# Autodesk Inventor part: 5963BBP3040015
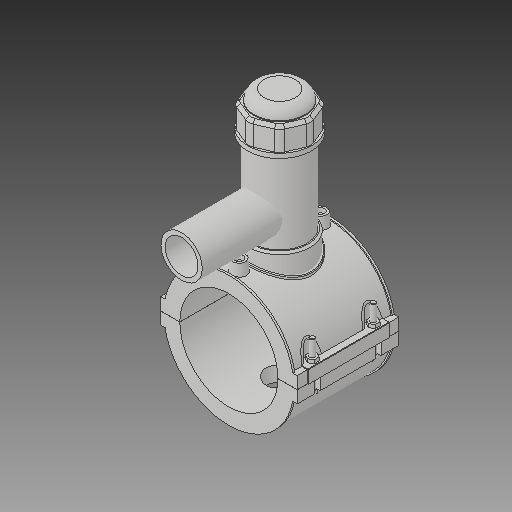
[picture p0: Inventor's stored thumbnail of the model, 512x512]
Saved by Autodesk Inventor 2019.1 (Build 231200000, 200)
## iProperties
Created: 2017-07
Part Number: 5963BBP3040015
Material: Generic
Description: PLASSON TAPPING SADDLE 4''IPS x 1 1/2''IPS
Document SubType Name: Modeling
Designer: KIM
Density: 1 g/cm^3
Appearance: Default
Author: KIM
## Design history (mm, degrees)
derived "5963BBP_5963BUP.ipt"
feature "Solid1::5963BBP_5963BUP.ipt"
feature "Solid2::5963BBP_5963BUP.ipt"
feature "Solid3::5963BBP_5963BUP.ipt"
tag "TaggingFeature1"
body "Solid1"
body "Solid2"
body "Solid3"
other parameters: "d0" = 114.1, "d2" = 159.004, "d3" = 28.525, "d4" = 118.11, "d5" = 0, "d6" = 0.1, "d8" = 0, "d19" = 6, "d20" = 6, "d21" = 70.866, "d23" = 0, "d24" = 35.433, "d26" = 0, "d27" = 3, "d28" = 3, "d29" = 3, "d30" = 38.03333, "d31" = 6, "d32" = 0, "d33" = 0, "d34" = 0.6, "d40" = 77.1316, "d41" = 74.165, "d43" = 0, "d45" = 0, "d47" = 145.031, "d70" = 15, "d72" = 0, "d73" = 6, "d75" = 5, "d76" = 0, "d77" = 5.705, "d78" = 87.05, "d79" = 15, "d80" = 47.244, "d82" = 5 deg, "d84" = 4, "d85" = 14, "d86" = 0, "d87" = 3, "d88" = 0, "d89" = 1, "d90" = 1, "d91" = 94.488, "d92" = 0, "d93" = 0.5, "d94" = 60.05263, "d96" = 151.2966, "d97" = 2.3622, "d98" = 0, "d102" = 1.141, "d120" = 140 deg, "d121" = 24.228, "d122" = 20 deg, "d123" = 296.66, "d124" = 88.998, "d126" = 0, "d143" = 117.523, "d145" = 26.33077, "d149" = 1.7115, "d150" = 28.96385, "d153" = 118.11, "d154" = 0, "d156" = 74.165, "d157" = 160 deg, "d159" = 6.846, "d161" = 1.7115, "d162" = 70.866, "d163" = 0, "d164" = 57.05, "d167" = 11.41, "d168" = 72.3561, "d170" = 3.2805, "d172" = 0, "d173" = 1, "d175" = 57.05, "d176" = 20 deg, "d177" = 7.987, "d178" = 34.23, "d180" = 0, "d183" = 13.692, "d184" = 6.3896, "d185" = 38.38575, "d186" = 38.38575, "d187" = 74.165, "d188" = 10.269, "d189" = 7.987, "d190" = 0, "d191" = 111.2475, "d193" = 6.9984, "d194" = 4.13385, "d195" = 90 deg, "d197" = 0, "d199" = 0, "d200" = 17.115, "d202" = 0, "d203" = 177.038, "d204" = 70.45675, "d205" = 51.9155, "d206" = 63.04025, "d207" = 132.7785, "d208" = 138.08964, "d209" = 164.64534, "d210" = 63.7819, "d211" = 74.165, "d212" = 59.332, "d213" = 36.8766, "d216" = 0, "d217" = 11.41, "d218" = 11.41, "d219" = 2.282, "d222" = 114.1, "d224" = 0, "d225" = 65.024, "d226" = 48.1, "d227" = 38.48, "d228" = 114.046, "d230" = 3.423, "d_" = 114.1, "B_" = 159.004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
